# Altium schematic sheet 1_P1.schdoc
size 1198 x 850 mm; Symbol: Sheet-Symbol_A4; Device: Sheet-Symbol_A4; Company: 嘉立创EDA; Version: V1.0; Page Size: A4; @Project Name: 紫金hulu; @Page Count: 1; @Update Date: 2024-11-23; @Create Date: 2024-09-02; @Schematic Name: Schematic1; @Page No: 1; @Page Name: P1; @Board Name: Board1; @Create Time: 22:13:04; @Update Time: 17:30:21; Width: 2338; Height: 1652; Region Start: 1; X Region Count: 6; Y Region Count: 4; Blade Width: 10; Title Block Position: 3
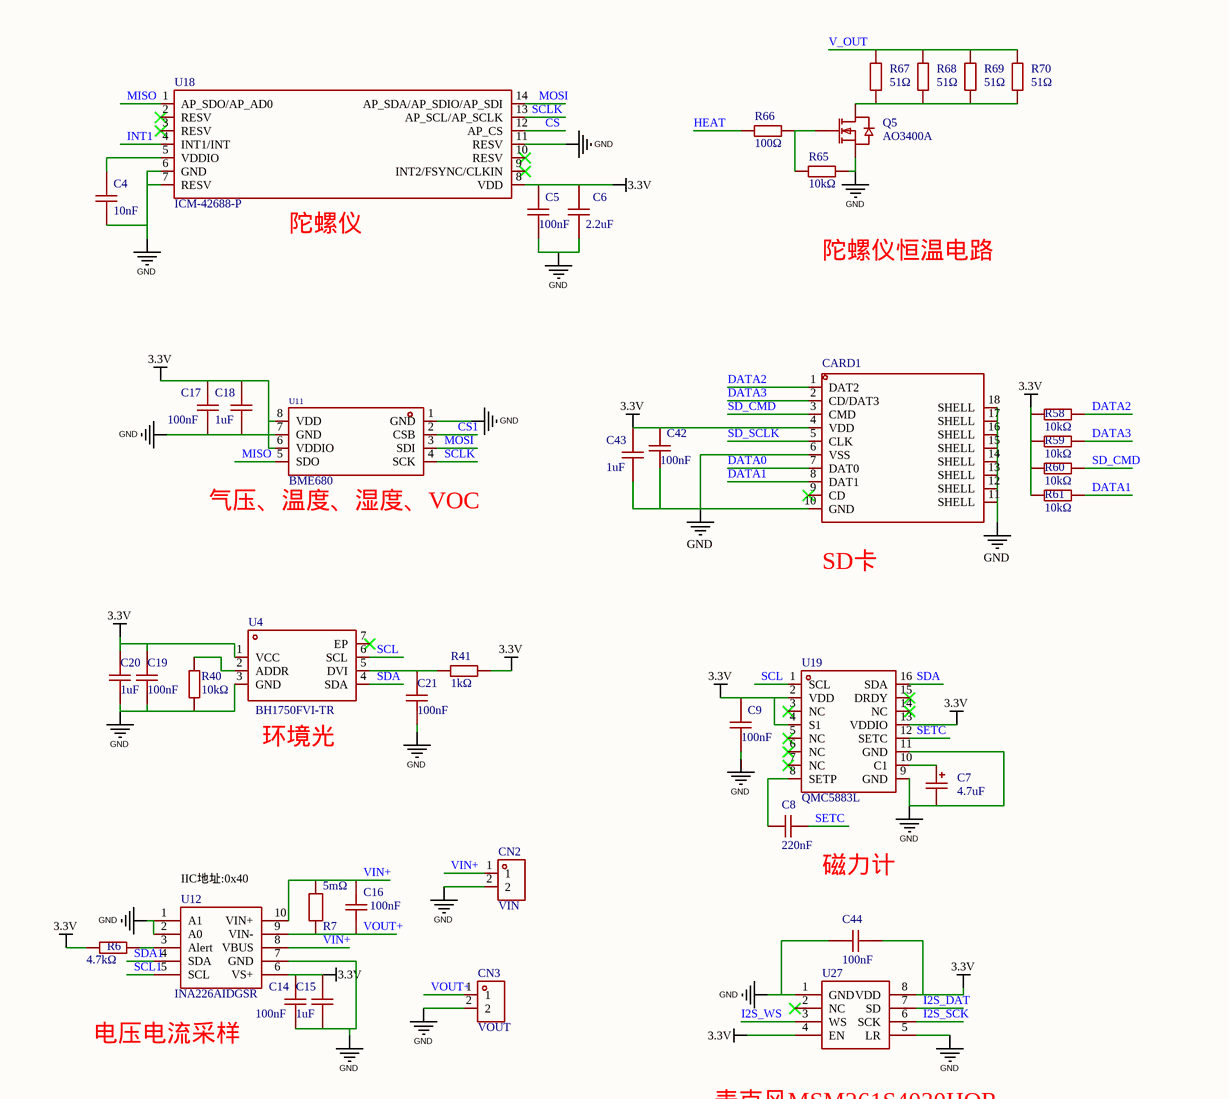
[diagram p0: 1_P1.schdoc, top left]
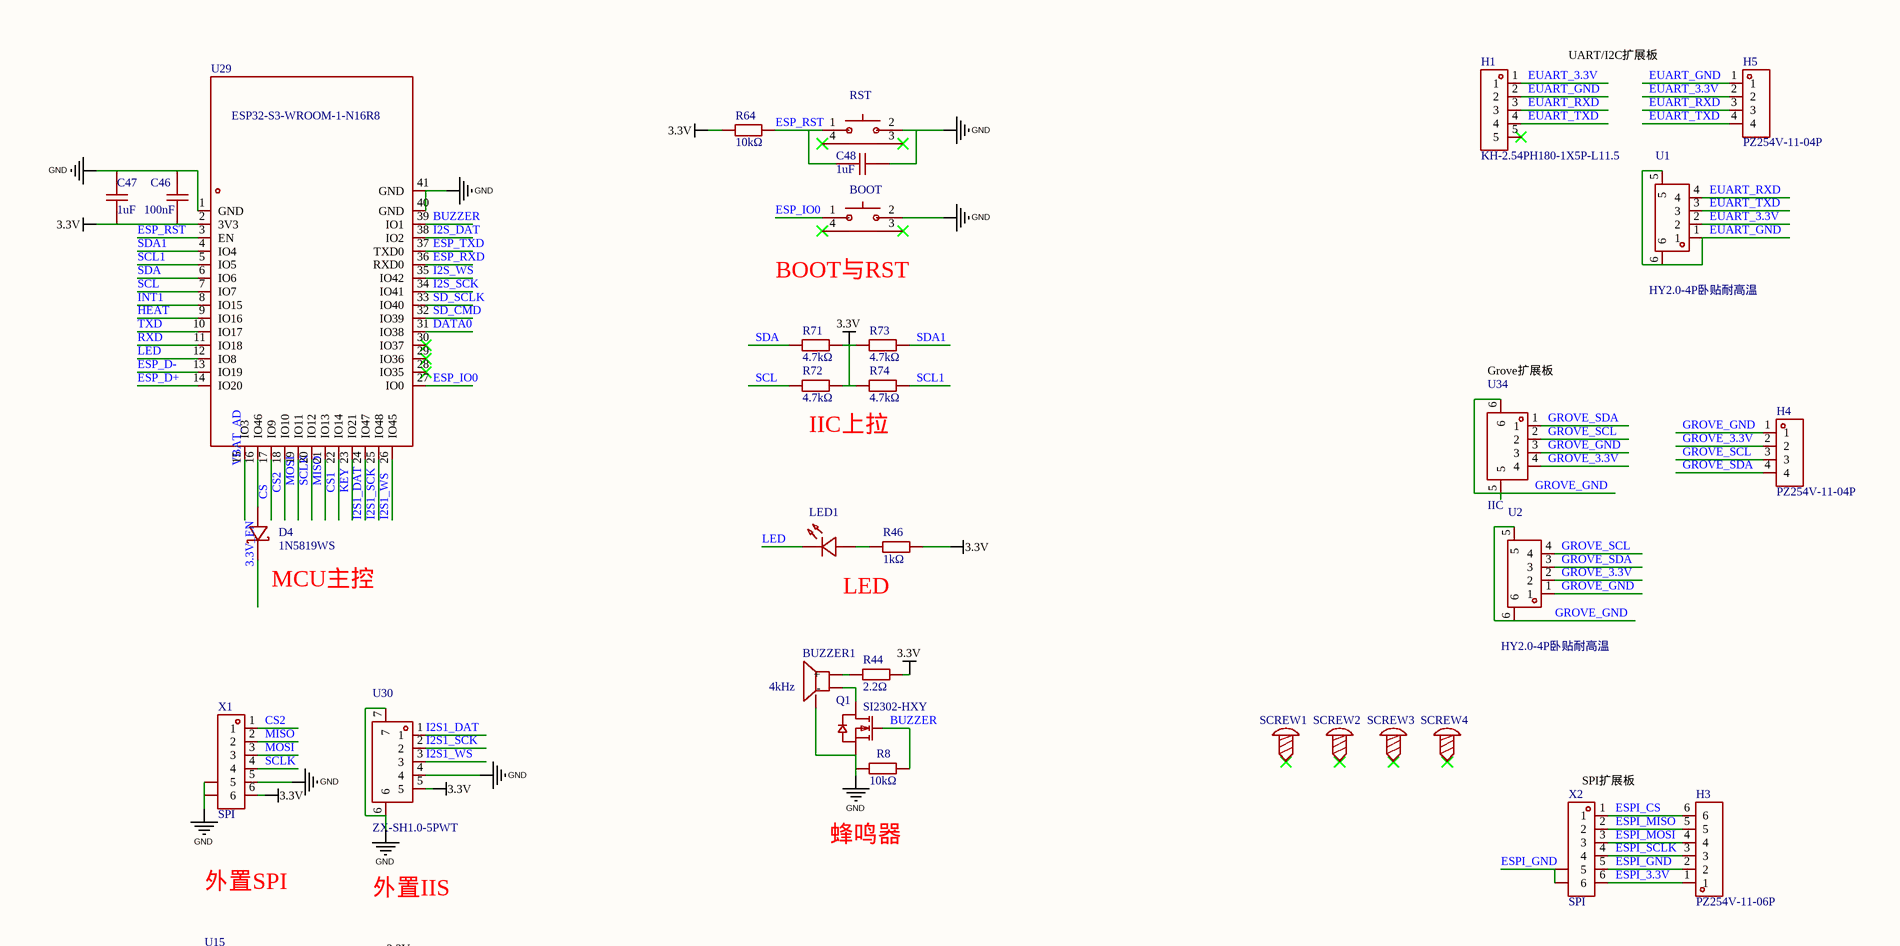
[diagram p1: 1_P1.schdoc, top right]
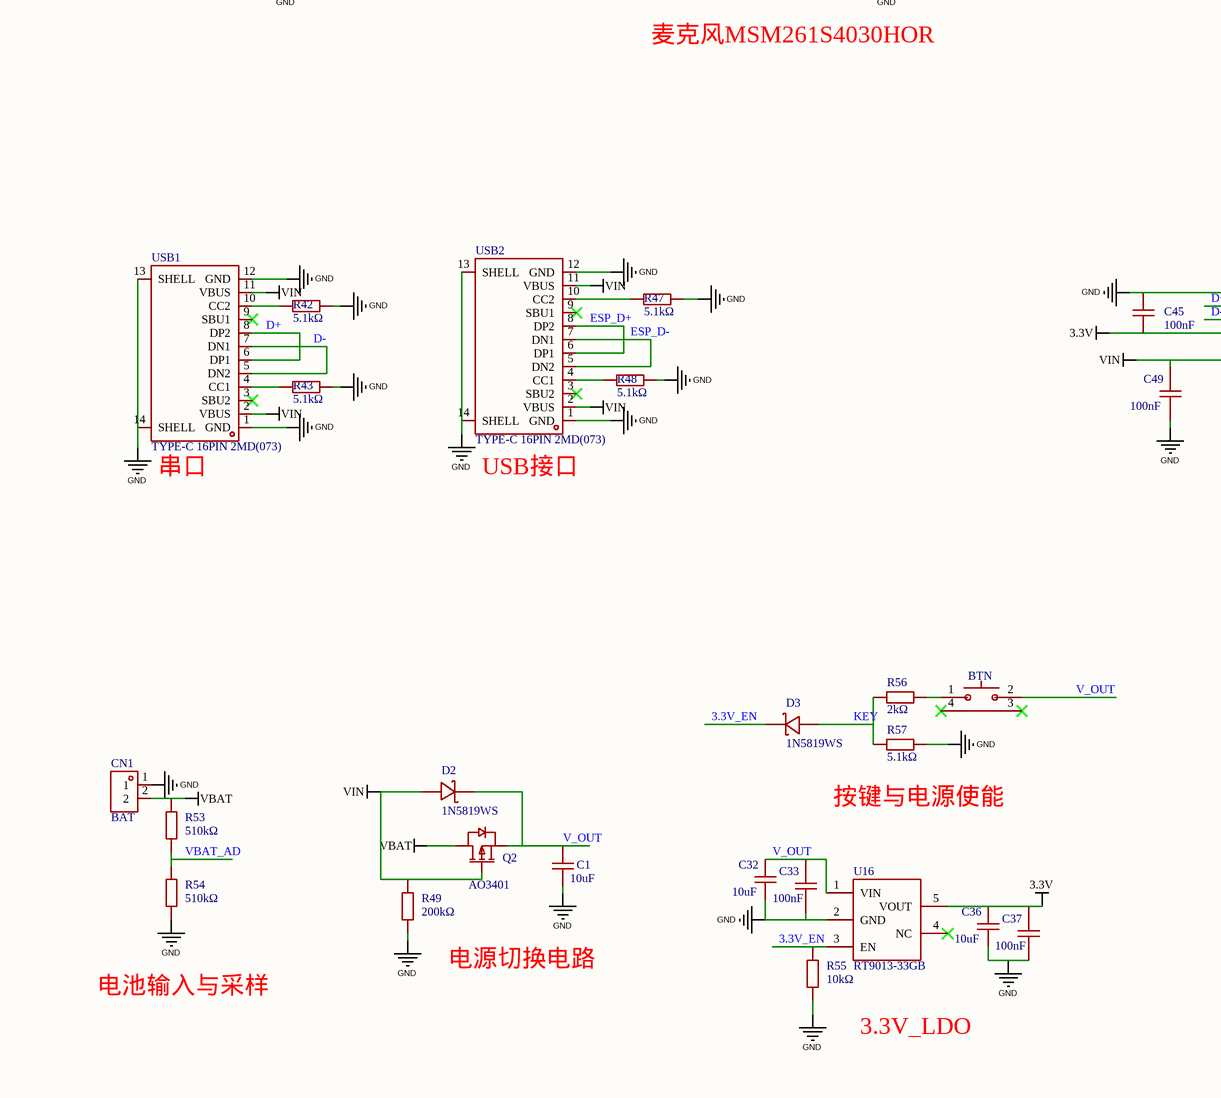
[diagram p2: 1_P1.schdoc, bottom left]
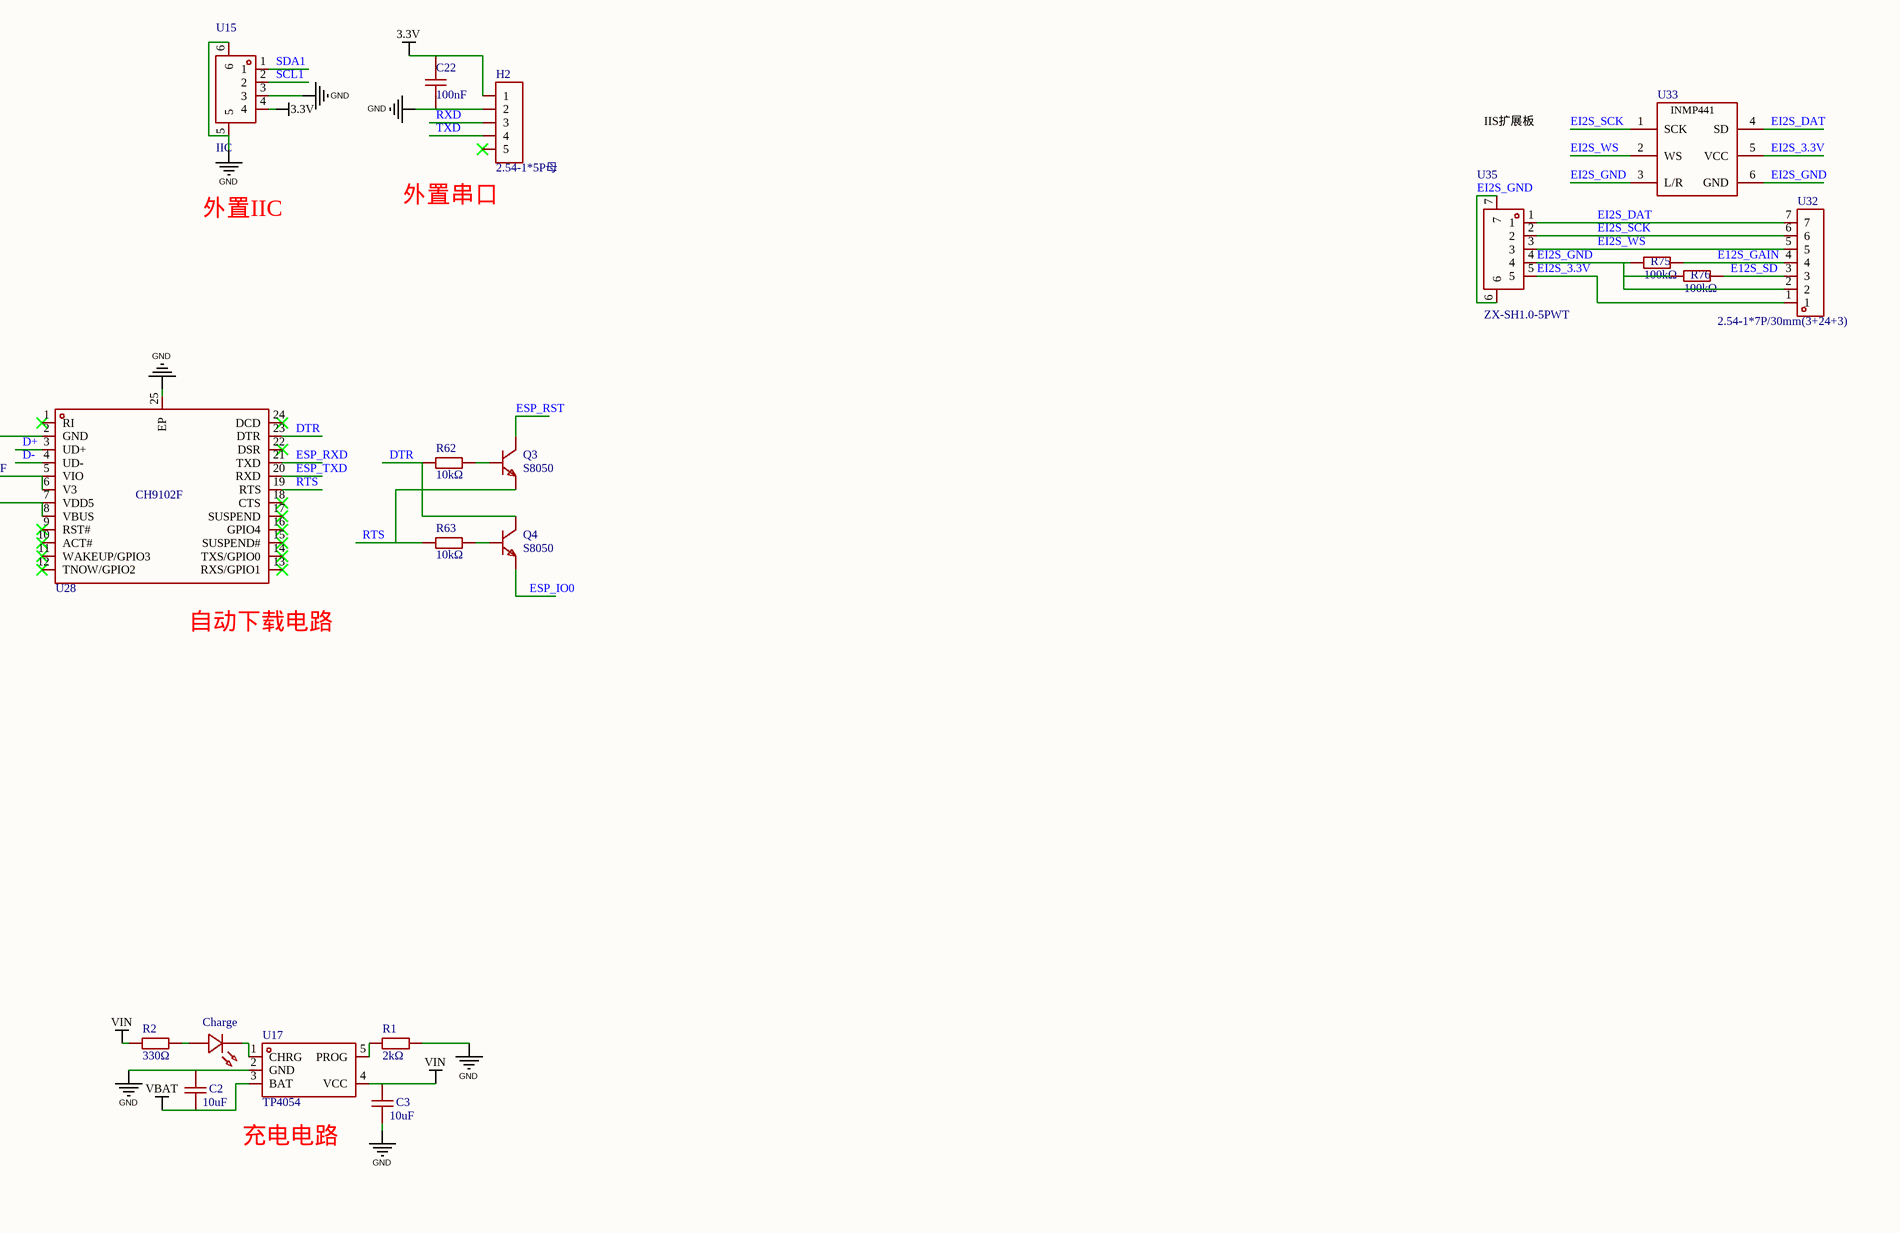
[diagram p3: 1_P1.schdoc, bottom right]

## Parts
BOOT  1TS003B-1800-3500A-CT  [SW-SMD_1TS003B-XXXX-3500A-CT]  (value not drawn)
BTN  1TS003B-1800-3500A-CT  [SW-SMD_1TS003B-XXXX-3500A-CT]  (value not drawn)
BUZZER1  4kHz  [BUZ-SMD_L5.0-W5.5-P4.60]  (value not drawn)
C1  10uF  [C0402]  (value not drawn)
C2  10uF  [C0402]  (value not drawn)
C3  10uF  [C0402]  (value not drawn)
C4  10nF  [C0402]  (value not drawn)
C5  100nF  [C0402]  (value not drawn)
C6  2.2uF  [C0402]  (value not drawn)
C7  4.7uF  [CASE-A_3216]  (value not drawn)
C8  220nF  [C0402]  (value not drawn)
C9  100nF  [C0402]  (value not drawn)
C14  100nF  [C0402]  (value not drawn)
C15  1uF  [C0402]  (value not drawn)
C16  100nF  [C0402]  (value not drawn)
C17  100nF  [C0402]  (value not drawn)
C18  1uF  [C0402]  (value not drawn)
C19  100nF  [C0402]  (value not drawn)
C20  1uF  [C0402]  (value not drawn)
C21  100nF  [C0402]  (value not drawn)
C22  100nF  [C0402]  (value not drawn)
C32  10uF  [C0402]  (value not drawn)
C33  100nF  [C0402]  (value not drawn)
C36  10uF  [C0402]  (value not drawn)
C37  100nF  [C0402]  (value not drawn)
C42  100nF  [C0402]
C43  1uF  [C0402]  (value not drawn)
C44  100nF  [C0402]  (value not drawn)
C45  100nF  [C0402]
C46  100nF  [C0402]  (value not drawn)
C47  1uF  [C0402]  (value not drawn)
C48  1uF  [C0402]  (value not drawn)
C49  100nF  [C0402]  (value not drawn)
CARD1  TF-110  [TF-SMD_TF-110]  (value not drawn)
Charge  XL-1608SURC-06  [LED0603-RD_RED]  (value not drawn)
CN1  BAT  [CONN-TH_2P-P2.5_XH2.54-2P_H]  (value not drawn)
CN2  VIN  [CONN-TH_2P-P2.5_XH2.54-2P_H]  (value not drawn)
CN3  VOUT  [CONN-TH_2P-P2.5_XH2.54-2P_H]  (value not drawn)
D2  1N5819WS  [SOD-323_L1.8-W1.3-LS2.5-RD]  (value not drawn)
D3  1N5819WS  [SOD-323_L1.8-W1.3-LS2.5-RD]  (value not drawn)
D4  1N5819WS  [SOD-323_L1.8-W1.3-LS2.5-RD]  (value not drawn)
H1  KH-2.54PH180-1X5P-L11.5  [HDR-TH_5P-P2.54-V-M]  (value not drawn)
H2  2.54-1*5P母  [HDR-TH_5P-P2.54-V-F]  (value not drawn)
H3  PZ254V-11-06P  [HDR-TH_6P-P2.54-V-M]  (value not drawn)
H4  PZ254V-11-04P  [HDR-TH_4P-P2.54-V-M]  (value not drawn)
H5  PZ254V-11-04P  [HDR-TH_4P-P2.54-V-M]  (value not drawn)
LED1  XL-1608SURC-06  [LED0603-RD_RED]  (value not drawn)
Q1  SI2302-HXY  [SOT-23-3_L2.9-W1.3-P1.90-LS2.4-BR]  (value not drawn)
Q2  AO3401  [SOT-23-3_L2.9-W1.4-P1.90-LS2.6-BR]  (value not drawn)
Q3  S8050  [SOT-23-3_L2.9-W1.6-P1.90-LS2.8-BR]  (value not drawn)
Q4  S8050  [SOT-23-3_L2.9-W1.6-P1.90-LS2.8-BR]  (value not drawn)
Q5  AO3400A  [SOT-23-3_L2.9-W1.3-P1.90-LS2.4-BR]  (value not drawn)
R1  2kΩ  [R0402]  (value not drawn)
R2  330Ω  [R0402]  (value not drawn)
R6  4.7kΩ  [R0402]  (value not drawn)
R7  5mΩ  [RES-SMD_L6.4-W3.2-R2512]  (value not drawn)
R8  10kΩ  [R0402]  (value not drawn)
R40  10kΩ  [R0402]  (value not drawn)
R41  1kΩ  [R0402]  (value not drawn)
R42  5.1kΩ  [R0402]  (value not drawn)
R43  5.1kΩ  [R0402]  (value not drawn)
R44  2.2Ω  [R0402]  (value not drawn)
R46  1kΩ  [R0402]  (value not drawn)
R47  5.1kΩ  [R0402]  (value not drawn)
R48  5.1kΩ  [R0402]  (value not drawn)
R49  200kΩ  [R0402]  (value not drawn)
R53  510kΩ  [R0402]  (value not drawn)
R54  510kΩ  [R0402]  (value not drawn)
R55  10kΩ  [R0402]  (value not drawn)
R56  2kΩ  [R0402]  (value not drawn)
R57  5.1kΩ  [R0402]  (value not drawn)
R58  10kΩ  [R0402]  (value not drawn)
R59  10kΩ  [R0402]  (value not drawn)
R60  10kΩ  [R0402]  (value not drawn)
R61  10kΩ  [R0402]  (value not drawn)
R62  10kΩ  [R0402]  (value not drawn)
R63  10kΩ  [R0402]  (value not drawn)
R64  10kΩ  [R0402]  (value not drawn)
R65  10kΩ  [R0402]  (value not drawn)
R66  100Ω  [R0402]  (value not drawn)
R67  51Ω  [R0603]  (value not drawn)
R68  51Ω  [R0603]  (value not drawn)
R69  51Ω  [R0603]  (value not drawn)
R70  51Ω  [R0603]  (value not drawn)
R71  4.7kΩ  [R0402]  (value not drawn)
R72  4.7kΩ  [R0402]  (value not drawn)
R73  4.7kΩ  [R0402]  (value not drawn)
R74  4.7kΩ  [R0402]  (value not drawn)
R75  100kΩ  [R0402]  (value not drawn)
R76  100kΩ  [R0402]  (value not drawn)
RST  1TS003B-1800-3500A-CT  [SW-SMD_1TS003B-XXXX-3500A-CT]  (value not drawn)
SCREW1  M2螺丝  [M2螺丝]  (value not drawn)
SCREW2  M2螺丝  [M2螺丝]  (value not drawn)
SCREW3  M2螺丝  [M2螺丝]  (value not drawn)
SCREW4  M2螺丝  [M2螺丝]  (value not drawn)
U1  HY2.0-4P卧贴耐高温  [CONN-SMD_C9900014118]  (value not drawn)
U2  HY2.0-4P卧贴耐高温  [CONN-SMD_C9900014118]  (value not drawn)
U4  BH1750FVI-TR  [WSOF-6_L2.6-W1.6-P0.50-TL-EP]  (value not drawn)
U11  BME680  [LGA-8_L3.0-W3.0-P0.80-TR]  (value not drawn)
U12  INA226AIDGSR  [MSOP-10_L3.0-W3.0-P0.50-LS5.0-BL]  (value not drawn)
U15  IIC  [CONN-SMD_4P-P1.00_MEGASTAR_ZX-SH1.0-4PWT]  (value not drawn)
U16  RT9013-33GB  [SOT-23-5_L3.0-W1.7-P0.95-LS2.8-BL]  (value not drawn)
U17  TP4054  [TSOT-23-5_L2.9-W1.6-P0.95-LS2.8-BR]  (value not drawn)
U18  ICM-42688-P  [LGA-14_L3.0-W2.5-P0.50-TL]  (value not drawn)
U19  QMC5883L  [LGA-16_L3.0-W3.0-P0.50-BL_SQ]  (value not drawn)
U27  MSM261S4030H0  [MSM-MIC]  (value not drawn)
U28  CH9102F  [QFN-24_L4.0-W4.0-P0.50-BL-EP2.5]  (value not drawn)
U29  ESP32-S3-WROOM-1-N16R8  [WIRELM-SMD_ESP32-S3-WROOM-1]  (value not drawn)
U30  ZX-SH1.0-5PWT  [CONN-SMD_5P-P1.00_MEGASTAR_ZX-SH1.0-5PWT]  (value not drawn)
U32  2.54-1*7P/30mm(3+24+3)  [HDR-TH_7P-P2.54-V-M-1]  (value not drawn)
U33  inmp441  [INMP441]  (value not drawn)
U34  IIC  [CONN-SMD_4P-P1.00_MEGASTAR_ZX-SH1.0-4PWT]  (value not drawn)
U35  ZX-SH1.0-5PWT  [CONN-SMD_5P-P1.00_MEGASTAR_ZX-SH1.0-5PWT]  (value not drawn)
USB1  TYPE-C 16PIN 2MD(073)  [USB-C-SMD_TYPE-C-6PIN-2MD-073]  (value not drawn)
USB2  TYPE-C 16PIN 2MD(073)  [USB-C-SMD_TYPE-C-6PIN-2MD-073]  (value not drawn)
X1  SPI  [CONN-SMD_AFC10-S06QCA-00]  (value not drawn)
X2  SPI  [CONN-SMD_AFC10-S06QCA-00]  (value not drawn)

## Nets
3.3V: C5.2 C6.2 C9.2 C14.2 C15.2 C17.2 C18.2 C19.2 C20.2 C22.2 C36.2 C37.2 C42.2 C43.2 C44.1 C45.1 C46.1 C47.1 CARD1.4(VDD) H2.1 R6.1 R41.2 R44.2 R46.2 R58.1 R59.1 R60.1 R61.1 R64.1 R71.2 R72.2 R73.1 R74.1 U4.1(VCC) U11.6(VDDIO) U11.8(VDD) U12.6(VS+) U15.4 U16.5(VOUT) U18.8(VDD) U19.2(VDD) U19.4(S1) U19.13(VDDIO) U27.4(EN) U27.8(VDD) U28.5(VIO) U28.6(V3) U29.2(3V3) U30.5 X1.6
GND: BOOT.2 BUZZER1.3(NC) C1.1 C2.2 C3.1 C4.2 C5.1 C6.1 C7.2 C9.1 C14.1 C15.1 C17.1 C18.1 C19.1 C20.1 C21.1 C22.1 C32.1 C33.1 C36.1 C37.1 C42.1 C43.1 C44.2 C45.2 C46.2 C47.2 C48.2 C49.1 CARD1.6(VSS) CARD1.10(GND) CARD1.11(SHELL) CARD1.12(SHELL) CARD1.13(SHELL) CARD1.14(SHELL) CARD1.15(SHELL) CARD1.16(SHELL) CARD1.17(SHELL) CARD1.18(SHELL) CN1.1 CN2.2 CN3.2 H2.2 Q1.2(S) Q5.2(S) R1.2 R8.1 R40.1 R42.2 R43.2 R47.2 R48.2 R49.1 R54.1 R55.1 R57.2 R65.2 RST.2 U4.3(GND) U11.1(GND) U11.7(GND) U12.1(A1) U12.2(A0) U12.7(GND) U15.3 U15.5 U15.6 U16.2(GND) U17.2(GND) U18.6(GND) U18.7(RESV) U18.11(RESV) U19.9(GND) U19.11(GND) U27.1(GND) U27.5(LR) U28.2(GND) U28.25(EP) U29.1(GND) U29.40(GND) U29.41(GND) U30.4 U30.6 U30.7 USB1.1(GND) USB1.12(GND) USB1.13(SHELL) USB1.14(SHELL) USB2.1(GND) USB2.12(GND) USB2.13(SHELL) USB2.14(SHELL) X1.5 X1.7 X1.8
VBAT: C2.1 CN1.2 Q2.3(D) R53.2 U17.3(BAT)
VIN: C3.2 C49.2 D2.2(A) Q2.1(G) R2.1 R49.2 U17.4(VCC) U28.7(VDD5) U28.8(VBUS) USB1.2(VBUS) USB1.11(VBUS) USB2.2(VBUS) USB2.11(VBUS)
3.3V_EN: D3.1(K) D4.1(K) R55.2 U16.3(EN)
BUZZER: Q1.1(G) R8.2 U29.39(IO1)
CS: U18.12(AP_CS) U29.17(IO9)
CS1: U11.2(CSB) U29.22(IO14)
CS2: U29.18(IO10) X1.1
D+: U28.3(UD+) USB1.6(DP1) USB1.8(DP2)
D-: U28.4(UD-) USB1.5(DN2) USB1.7(DN1)
DATA0: CARD1.7(DAT0) U29.31(IO38)
DATA1: CARD1.8(DAT1) R61.2
DATA2: CARD1.1(DAT2) R58.2
DATA3: CARD1.2(CD/DAT3) R59.2
DTR: Q4.3 R62.1 U28.23(DTR)
E12S_GAIN: R75.2 U32.4
E12S_SD: R76.2 U32.3
EI2S_3.3V: U32.1 U33.5(VCC) U35.5
EI2S_DAT: U32.7 U33.4(SD) U35.1
EI2S_GND: R75.1 R76.1 U32.2 U33.3(L/R) U33.6(GND) U35.4 U35.6 U35.7
EI2S_SCK: U32.6 U33.1(SCK) U35.2
EI2S_WS: U32.5 U33.2(WS) U35.3
ESP_D+: U29.14(IO20) USB2.6(DP1) USB2.8(DP2)
ESP_D-: U29.13(IO19) USB2.5(DN2) USB2.7(DN1)
ESP_IO0: BOOT.1 Q4.2 U29.27(IO0)
ESP_RST: C48.1 Q3.3 R64.2 RST.1 U29.3(EN)
ESP_RXD: U28.21(TXD) U29.36(RXD0)
ESP_TXD: U28.20(RXD) U29.37(TXD0)
ESPI_3.3V: H3.1 X2.6
ESPI_CS: H3.6 X2.1
ESPI_GND: H3.2 X2.5 X2.7 X2.8
ESPI_MISO: H3.5 X2.2
ESPI_MOSI: H3.4 X2.3
ESPI_SCLK: H3.3 X2.4
EUART_3.3V: H1.1 H5.2 U1.2
EUART_GND: H1.2 H5.1 U1.1 U1.5 U1.6
EUART_RXD: H1.3 H5.3 U1.4
EUART_TXD: H1.4 H5.4 U1.3
GROVE_3.3V: H4.2 U2.2 U34.4
GROVE_GND: H4.1 U2.1 U2.5 U2.6 U34.3 U34.5 U34.6
GROVE_SCL: H4.3 U2.4 U34.2
GROVE_SDA: H4.4 U2.3 U34.1
HEAT: R66.1 U29.9(IO16)
I2S1_DAT: U29.24(IO47) U30.1
I2S1_SCK: U29.25(IO48) U30.2
I2S1_WS: U29.26(IO45) U30.3
I2S_DAT: U27.7(SD) U29.38(IO2)
I2S_SCK: U27.6(SCK) U29.34(IO41)
I2S_WS: U27.3(WS) U29.35(IO42)
INT1: U18.4(INT1/INT) U29.8(IO15)
KEY: D3.2(A) R56.2 R57.1 U29.23(IO21)
LED: LED1.1(K) U29.12(IO8)
MISO: U11.5(SDO) U18.1(AP_SDO/AP_AD0) U29.21(IO13) X1.2
MOSI: U11.3(SDI) U18.14(AP_SDA/AP_SDIO/AP_SDI) U29.19(IO11) X1.3
RTS: Q3.2 R63.1 U28.19(RTS)
RXD: H2.3 U29.11(IO18)
SCL: R72.1 U4.6(SCL) U19.1(SCL) U29.7(IO7)
SCL1: R74.2 U12.5(SCL) U15.2 U29.5(IO5)
SCLK: U11.4(SCK) U18.13(AP_SCL/AP_SCLK) U29.20(IO12) X1.4
SD_CMD: CARD1.3(CMD) R60.2 U29.32(IO39)
SD_SCLK: CARD1.5(CLK) U29.33(IO40)
SDA: R71.1 U4.4(SDA) U19.16(SDA) U29.6(IO6)
SDA1: R73.2 U12.4(SDA) U15.1 U29.4(IO4)
SETC: C8.2 U19.12(SETC)
TXD: H2.4 U29.10(IO17)
V_OUT: BTN.2 C1.2 C32.2 C33.2 D2.1(K) Q2.2(S) R67.2 R68.2 R69.2 R70.2 U16.1(VIN)
VBAT_AD: R53.1 R54.2 U29.15(IO3)
VIN+: C16.2 CN2.1 R7.2 U12.8(VBUS) U12.10(VIN+)
VOUT+: C16.1 CN3.1 R7.1 U12.9(VIN-)
NetBTN_1: BTN.1 R56.1
NetBUZZER1_1: BUZZER1.1(+) R44.1
NetBUZZER1_2: BUZZER1.2(-) Q1.3(D)
NetC4_1: C4.1 U18.5(VDDIO)
NetC7_1: C7.1 U19.10(C1)
NetC8_1: C8.1 U19.8(SETP)
NetC21_2: C21.2 R41.1 U4.5(DVI)
NetCharge_1: Charge.1(K) U17.1(CHRG)
NetCharge_2: Charge.2(A) R2.2
NetD4_2: D4.2(A) U29.16(IO46)
NetLED1_2: LED1.2(A) R46.1
NetQ3_1: Q3.1 R62.2
NetQ4_1: Q4.1 R63.2
NetQ5_1: Q5.1(G) R65.1 R66.2
NetQ5_3: Q5.3(D) R67.1 R68.1 R69.1 R70.1
NetR1_1: R1.1 U17.5(PROG)
NetR6_2: R6.2 U12.3(Alert)
NetR40_2: R40.2 U4.2(ADDR)
NetR42_1: R42.1 USB1.10(CC2)
NetR43_1: R43.1 USB1.4(CC1)
NetR47_1: R47.1 USB2.10(CC2)
NetR48_1: R48.1 USB2.4(CC1)

Not connected (* = marked no-connect by the designer): BOOT 3* 4*; BTN 3* 4*; CARD1 9(CD)*; H1 5*; H2 5*; RST 3* 4*; SCREW1 1*; SCREW2 1*; SCREW3 1*; SCREW4 1*; U4 7(EP)*; U16 4(NC)*; U18 2(RESV)* 3(RESV)* 9(INT2/FSYNC/CLKIN)* 10(RESV)*; U19 3(NC)* 5(NC)* 6(NC)* 7(NC)* 14(NC)* 15(DRDY)*; U27 2(NC)*; U28 1(RI)* 9(RST#)* 10(ACT#)* 11(WAKEUP/GPIO3)* 12(TNOW/GPIO2)* 13(RXS/GPIO1)* 14(TXS/GPIO0)* 15(SUSPEND#)* 16(GPIO4)* 17(SUSPEND)* 18(CTS)* 22(DSR)* 24(DCD)*; U29 28(IO35)* 29(IO36)* 30(IO37)*; USB1 3(SBU2)* 9(SBU1)*; USB2 3(SBU2)* 9(SBU1)*

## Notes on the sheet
- UART/I2C扩展板
- (near U18) 陀螺仪
- 陀螺仪恒温电路
- (near BOOT) BOOT与RST
- (near U34) Grove扩展板
- IIC上拉
- (near U11) 气压、温度、湿度、VOC
- (near CARD1) SD卡
- (near D4) MCU主控
- LED
- (near U4) 环境光
- (near X2) SPI扩展板
- 蜂鸣器
- (near U12) IIC地址:0x40
- 磁力计
- 外置SPI
- 外置IIS
- 电压电流采样
- IIS扩展板
- 麦克风MSM261S4030HOR
- 外置IIC
- 外置串口
- (near USB1) 串口
- (near USB2) USB接口
- (near U28) 自动下载电路
- (near R57) 按键与电源使能
- 电池输入与采样
- (near R49) 电源切换电路
- 3.3V_LDO
- 充电电路

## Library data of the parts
BOOT BTN RST = 1TS003B-1800-3500A-CT: 电路结构:单刀单掷;按钮形状:矩形按钮;作用力:180gf;安装方式:卧贴;开关长度:4.6mm;开关宽度:1.82mm;开关高度:3.5mm;带支架:不带;触点电流:50mA;额定电压(AC):-;额定电压(DC):12V;额定功率:0.6W;绝缘电阻:100MΩ;带灯:无;机械寿命:5万次;; Manufacturer: HYP(鸿源精密); Add into BOM: yes; Circuit: 单刀单掷; Actuator Style: 矩形按钮; Operating Force: 180gf; Switch Length: 4.6mm; Switch Width: 1.82mm; Switch Height: 3.5mm; Strike Gundam: 不带; Contact Current: 50mA; Voltage Rating (DC): 12V; Power Rating: 0.6W; Insulation Resistance: 100MΩ; Actuator/Cap Color: 黑色; With Lamp: 无; Pin Style: J型引脚; Mechanical Life: 5万次
BUZZER1 = MLT-5020: 驱动方式:无源(外部驱动);构造类型:电磁式;频率:4kHz;; Manufacturer: 华能; Add into BOM: yes; Technology Type: 电磁式
C1-C3 C32 C36 = CL05A106MQ5NUNC: 容值:10uF;精度:±20%;额定电压:6.3V;材质(温度系数):X5R;; Manufacturer: SAMSUNG(三星); Add into BOM: yes; Tolerance: ±20%; Voltage Rated: 6.3V; Temperature Coefficient: X5R
C4 = CC0402KRX7R7BB103: 容值:10nF;精度:±10%;额定电压:16V;材质(温度系数):X7R;; Manufacturer: YAGEO(国巨); Add into BOM: yes; Tolerance: ±10%; Voltage Rated: 16V; Temperature Coefficient: X7R
C5 C9 C14 C16 C17 C19 C21 C22 C33 C37 C44 C46 C49 = CC0402KRX7R7BB104: 容值:100nF;精度:±10%;额定电压:16V;材质(温度系数):X7R;; Manufacturer: YAGEO(国巨); Add into BOM: yes; Tolerance: ±10%; Voltage Rated: 16V; Temperature Coefficient: X7R
C6 = GRM155R61E225KE11D: 容值:2.2uF;精度:±10%;额定电压:25V;材质(温度系数):X5R;; Manufacturer: muRata(村田); Add into BOM: yes; Tolerance: ±10%; Voltage Rated: 25V; Temperature Coefficient: X5R
C7 = TAJA475K016RNJ: 容值:4.7uF;精度:±10%;额定电压:16V;等效串联电阻:4Ω@100kHz;; Manufacturer: Kyocera AVX; Add into BOM: yes; Tolerance: ±10%; Rated Voltage: 16V
C8 = CL05B224KO5NNNC: 容值:220nF;精度:±10%;额定电压:16V;材质(温度系数):X7R;; Manufacturer: SAMSUNG(三星); Add into BOM: yes; Tolerance: ±10%; Voltage Rated: 16V; Temperature Coefficient: X7R
C15 C18 C20 C43 C47 C48 = C1005X5R105KCTS: 容值:1uF;精度:±10%;额定电压:6.3V;材质(温度系数):X5R;; Manufacturer: DARFON(达方); Add into BOM: yes; Tolerance: ±10%; Voltage Rated: 6.3V; Temperature Coefficient: X5R
C42 C45 = 0603B104K500NT: 容值:100nF;精度:±10%;额定电压:50V;材质(温度系数):X7R;; Manufacturer: FH(风华); Add into BOM: yes; Tolerance: ±10%; Voltage Rated: 50V; Temperature Coefficient: X7R
CARD1 = TF-110: 卡连接方式:拔插式;卡类型:MicroSD卡(TF卡);连接器类型:卡座;本体最大高度:1.32mm;触头材质:磷铜;触头镀层:金;工作温度范围:-45~+85;焊接温度(最大值):260;; Manufacturer: XUNPU(讯普); Add into BOM: yes; Card Connection Mode: 拔插式; Connector Type: 卡座; Maximum Body Height: 1.32mm; Welding Temperature (Max): 260
Charge LED1 = XL-1608SURC-06: 发光颜色:红色;功率:55mW;正向电流:25mA;主波长:617nm~621nm;透镜颜色:无色透明透镜;色温:-;发光角度:120°;载带方式:正贴;工作温度:-30℃~+85℃;; Manufacturer: XINGLIGHT(成兴光); Add into BOM: yes; Emitted Color: 红色; Power Dissipation: 55mW; Forward Current: 25mA; Peak Wavelength: 623nm; Lens Color: 无色透明透镜; Viewing Angle: 120°; Mounting Sytle: 正贴
CN1-CN3 = XH2.54-2P_H弯针插座: Add into BOM: yes
D2-D4 = 1N5819WS_C191023: 正向压降(Vf):600mV@1A;直流反向耐压(Vr):40V;平均整流电流(Io):1A;; Manufacturer: Hottech(合科泰); Add into BOM: yes; Reverse Voltage (Vr): 40V; Average Rectified Current (Io): 1A
H1 = KH-2.54PH180-1X5P-L11.5: 插针结构:1x5P;间距:2.54mm;行距:-;圆针/方针:方针;安装类型:直插;排数:单排;总PIN位数:5P;额定电流:3A;额定电压:-;配合针长度:6mm;塑高:2.5mm;端接针长度:3mm;工作温度范围:-40℃~+105℃;颜色:黑色;; Manufacturer: kinghelm(金航标); Add into BOM: yes; Pin Structure: 1x5P; Pitch: 2.54mm; Circluar Pins/Square Pins: 方针; Current Rating (Max): 3A
H2 = 2.54-1*5P母: 插孔结构:1x5P;间距:2.54mm;行距:-;安装类型:直插;排数:单排;总孔位数:5P;塑高:-;触头材质:-;触头镀层:-;; Manufacturer: BOOMELE(博穆精密); Symbol: Header-Female-2.54_1x5; Add into BOM: yes; Holes Structure: 1x5P; Pitch: 2.54mm; Number of Holes: 5P
H3 = PZ254V-11-06P: 插针结构:1x6P;间距:2.54mm;行距:-;圆针/方针:方针;安装类型:直插;排数:单排;总PIN位数:6P;额定电流:-;额定电压:-;配合针长度:6mm;塑高:2.5mm;端接针长度:3mm;触头材质:黄铜;触头镀层:-;工作温度范围:-40℃~+105℃;颜色:黑色;; Manufacturer: XFCN(兴飞); Add into BOM: yes; Pin Structure: 1x6P; Pitch: 2.54mm; Circluar Pins/Square Pins: 方针
H4 H5 = PZ254V-11-04P: 插针结构:1x4P;间距:2.54mm;行距:-;圆针/方针:方针;安装类型:直插;排数:单排;总PIN位数:4P;额定电流:3A;额定电压:250V;配合针长度:6mm;塑高:2.5mm;端接针长度:3mm;触头材质:-;工作温度范围:-40℃~+105℃;颜色:黑色;; Manufacturer: XFCN(兴飞); Symbol: PZ254V-11-04P_C2691448; Add into BOM: yes; Pin Structure: 1x4P; Pitch: 2.54mm; Circluar Pins/Square Pins: 方针; Current Rating (Max): 3A; Voltage Rating (Max): 250V
Q1 = SI2302-HXY: 类型:1个N沟道;漏源电压(Vdss):20V;连续漏极电流(Id):2.8A;功率(Pd):900mW;导通电阻(RDS(on)@Vgs,Id):55mΩ@4.5V,2.8A;阈值电压(Vgs(th)@Id):1.2V@250uA;; Manufacturer: HXY MOSFET(华轩阳电子); Symbol: SI2302_C4748714; Add into BOM: yes; Type: 1个N沟道; Drain Source Voltage (Vdss): 20V; Power Dissipation (Pd): 900mW; Input Capacitance (Ciss@Vds): 260pF@10V
Q2 = AO3401_C727156: 类型:1个P沟道;漏源电压(Vdss):30V;连续漏极电流(Id):4.2A;功率(Pd):350mW;导通电阻(RDS(on)@Vgs,Id):65mΩ@10V,4.2A;阈值电压(Vgs(th)@Id):1.3V@250uA;; Manufacturer: TWGMC(台湾迪嘉); Add into BOM: yes; Type: 1个P沟道; Drain Source Voltage (Vdss): 30V; Power Dissipation (Pd): 350mW
Q3 Q4 = S8050_C181158: 晶体管类型:NPN;集电极电流(Ic):500mA;集射极击穿电压(Vceo):25V;功率(Pd):300mW;; Manufacturer: Hottech(合科泰); Add into BOM: yes; Transistor Type: NPN; Collector Current (Ic): 500mA; Collector-Emitter Breakdown Voltage (Vceo): 25V; Power Dissipation (Pd): 300mW; Transition Frequency (fT): 150MHz; Collector Cut-Off Current (Icbo): 100nA; Collector-Emitter Saturation Voltage (VCE(sat)@Ic,Ib): 600mV@500mA,50mA
Q5 = AO3400A_C20917: 类型:1个N沟道;漏源电压(Vdss):30V;连续漏极电流(Id):5.7A;功率(Pd):1.4W;导通电阻(RDS(on)@Vgs,Id):26.5mΩ@10V,5.7A;阈值电压(Vgs(th)@Id):1.5V@250uA;; Manufacturer: AOS; Add into BOM: yes; Type: 1个N沟道; Drain Source Voltage (Vdss): 30V; Power Dissipation (Pd): 1.4W; Total Gate Charge (Qg@Vgs): 7nC@4.5V; Input Capacitance (Ciss@Vds): 630pF@15V
R1 R56 = 0402WGF2001TCE: 电阻类型:厚膜电阻;阻值:2kΩ;精度:±1%;功率:62.5mW;最大工作电压:50V;温度系数:±100ppm/℃;; Manufacturer: UNI-ROYAL(厚声); Add into BOM: yes; Tolerance: ±1%; Power(Watts): 62.5mW; Overload Voltage (Max): 50V
R2 = 0402WGF3300TCE: 电阻类型:厚膜电阻;阻值:330Ω;精度:±1%;功率:62.5mW;最大工作电压:50V;温度系数:±100ppm/℃;; Manufacturer: UNI-ROYAL(厚声); Add into BOM: yes; Tolerance: ±1%; Power(Watts): 62.5mW; Overload Voltage (Max): 50V
R6 = RTT02472JTH: 电阻类型:厚膜电阻;阻值:4.7kΩ;精度:±5%;功率:62.5mW;最大工作电压:50V;温度系数:±100ppm/℃;; Manufacturer: RALEC(旺诠); Add into BOM: yes; Tolerance: ±5%; Power(Watts): 62.5mW; Overload Voltage (Max): 50V
R7 = LRAN25EJER005: 电阻类型:采样电阻;阻值:5mΩ;精度:±5%;功率:2W;; Manufacturer: NCT(利昇达); Add into BOM: yes; Tolerance: ±5%; Power(Watts): 2W
R8 R40 R55 R58-R65 = RC0402FR-0710KL: 电阻类型:厚膜电阻;阻值:10kΩ;精度:±1%;功率:62.5mW;最大工作电压:50V;温度系数:±100ppm/℃;; Manufacturer: YAGEO(国巨); Add into BOM: yes; Tolerance: ±1%; Power(Watts): 62.5mW; Overload Voltage (Max): 50V
R41 R46 = 0402WGF1001TCE: 电阻类型:厚膜电阻;阻值:1kΩ;精度:±1%;功率:62.5mW;最大工作电压:50V;温度系数:±100ppm/℃;; Manufacturer: UNI-ROYAL(厚声); Add into BOM: yes; Tolerance: ±1%; Power(Watts): 62.5mW; Overload Voltage (Max): 50V
R42 R43 R47 R48 R57 = 0402WGF5101TCE: 电阻类型:厚膜电阻;阻值:5.1kΩ;精度:±1%;功率:62.5mW;最大工作电压:50V;温度系数:±100ppm/℃;; Manufacturer: UNI-ROYAL(厚声); Add into BOM: yes; Tolerance: ±1%; Power(Watts): 62.5mW; Overload Voltage (Max): 50V
R44 = 0402WGF220KTCE: 电阻类型:厚膜电阻;阻值:2.2Ω;精度:±1%;功率:62.5mW;最大工作电压:50V;温度系数:±200ppm/℃;; Manufacturer: UNI-ROYAL(厚声); Add into BOM: yes; Tolerance: ±1%; Power(Watts): 62.5mW; Overload Voltage (Max): 50V
R49 = 0402WGF2003TCE: 电阻类型:厚膜电阻;阻值:200kΩ;精度:±1%;功率:62.5mW;最大工作电压:50V;温度系数:±100ppm/℃;; Manufacturer: UNI-ROYAL(厚声); Add into BOM: yes; Tolerance: ±1%; Power(Watts): 62.5mW; Overload Voltage (Max): 50V
R53 R54 = 0402WGF5103TCE: 电阻类型:厚膜电阻;阻值:510kΩ;精度:±1%;功率:62.5mW;最大工作电压:50V;温度系数:±100ppm/℃;; Manufacturer: UNI-ROYAL(厚声); Add into BOM: yes; Tolerance: ±1%; Power(Watts): 62.5mW; Overload Voltage (Max): 50V
R66 = 0402WGJ0101TCE: 电阻类型:厚膜电阻;阻值:100Ω;精度:±5%;功率:62.5mW;最大工作电压:50V;温度系数:±100ppm/℃;; Manufacturer: UNI-ROYAL(厚声); Add into BOM: yes; Tolerance: ±5%; Power(Watts): 62.5mW; Overload Voltage (Max): 50V
R67-R70 = 0603WAF510JT5E: 电阻类型:厚膜电阻;阻值:51Ω;精度:±1%;功率:100mW;最大工作电压:75V;温度系数:±100ppm/℃;; Manufacturer: UNI-ROYAL(厚声); Add into BOM: yes; Tolerance: ±1%; Power(Watts): 100mW; Overload Voltage (Max): 75V
R71-R74 = 0402WGJ0472TCE: 电阻类型:厚膜电阻;阻值:4.7kΩ;精度:±5%;功率:62.5mW;最大工作电压:50V;温度系数:±100ppm/℃;; Manufacturer: UNI-ROYAL(厚声); Add into BOM: yes; Tolerance: ±5%; Power(Watts): 62.5mW; Overload Voltage (Max): 50V
R75 R76 = 0402WGF1003TCE: 电阻类型:厚膜电阻;阻值:100kΩ;精度:±1%;功率:62.5mW;最大工作电压:50V;温度系数:±100ppm/℃;; Manufacturer: UNI-ROYAL(厚声); Add into BOM: yes; Tolerance: ±1%; Power(Watts): 62.5mW; Overload Voltage (Max): 50V
SCREW1-SCREW4 = M2螺丝: Symbol: 螺丝孔; Convert to PCB: yes
U1 U2 = HY2.0-4P卧贴耐高温: Add into BOM: yes
U4 = BH1750FVI-TR: 检测颜色:-;接口类型:I2C;分辨率(位):16;; Manufacturer: ROHM(罗姆); Add into BOM: yes; Interface Type: I2C; Supply Voltage: 2.4V~3.6V; Resolution: 16
U11 = BME680: 气体，湿度，压力，温度传感器; Manufacturer: Bosch(博世); Add into BOM: yes
U12 = INA226AIDGSR: INA226 支持报警功能的 36V、双向、超高精度、低侧/高侧、I2C 输出电流/功率监控器; Manufacturer: TI(德州仪器); Add into BOM: yes; Supply Voltage: 0V~36V
U15 U34 = ZX-SH1.0-4PWT: 插针结构:1x4P;间距:1mm;安装方式:卧贴;参考系列:SH;总PIN数:4P;排数:1;每排PIN数:4;行距:-;额定电流:1A;触头材质:黄铜;触头镀层:锡;工作温度范围:-25℃~+85℃;; Manufacturer: Megastar(兆星); Add into BOM: yes; Pins Structure: 1x4P; Pitch: 1mm; Reference Series: SH; Number of PINs Per Row: 4; Current Rating (Max): 1A
U16 = RT9013-33GB: 输出类型:固定;最大输入电压:5.5V;输出电压:3.3V;最大输出电流:500mA;电源纹波抑制比(PSRR):50dB@(10kHz);输出极性:正极;; Manufacturer: RICHTEK(立锜); Add into BOM: yes; Output Type: 固定; Maximum Input Voltage: 5.5V; Output Voltage: 3.3V; MAX Output Current: 500mA; Dropout Voltage: 400mV@(500mA); standby current: 50uA; Output Polarity: 正极; Number of Outputs: 1
U17 = TP4054_C668215: 电源电压:6.5V;最大充电电流:500mA;电池类型:锂离子/聚合物;电池节数:1;; Manufacturer: UMW(友台半导体); Add into BOM: yes; Supply Voltage: 6.5V; Maximum Charge Current: 500mA; Number of Cells: 1
U18 = ICM-42688-P: 传感器类型:加速度计陀螺仪;; Manufacturer: TDK InvenSense(应美盛); Add into BOM: yes
U19 = QMC5883L: Manufacturer: QST(上海矽睿); Add into BOM: yes
U27 = MSM261S4030H0: Add into BOM: yes
U28 = CH9102F: Manufacturer: WCH(南京沁恒); Add into BOM: yes
U29 = ESP32-S3-WROOM-1-N16R8: Manufacturer: ESPRESSIF(乐鑫); Symbol: ESP32-S3-WROOM-1(N16R8); Add into BOM: yes
U30 U35 = ZX-SH1.0-5PWT: 插针结构:1x5P;间距:1mm;安装方式:卧贴;参考系列:SH;总PIN数:5P;排数:1;每排PIN数:5;行距:-;额定电流:1A;触头材质:黄铜;触头镀层:锡;工作温度范围:-25℃~+85℃;; Manufacturer: Megastar(兆星); Add into BOM: yes; Pins Structure: 1x5P; Pitch: 1mm; Reference Series: SH; Number of PINs Per Row: 5; Current Rating (Max): 1A
U32 = 2.54-1*7P/30mm(3+24+3): Add into BOM: yes
U33 = inmp441: Symbol: inmp441_数字麦克风; Add into BOM: yes
USB1 USB2 = TYPE-C 16PIN 2MD(073): 连接器类型:Type-C;标准:-;公母:母;端口数量:1;触点数量:16P;安装方式:卧贴;额定电流 - 电源:5A;工作温度范围:-25℃~+85℃;; Manufacturer: SHOU HAN(首韩); Add into BOM: yes; Gender: 母; Number of Ports: 1; Number of Contacts: 16P; Current Rating - Power (Max): 5A
X1 X2 = AFC10-S06QCA-00: 插针结构:1x6P;间距:1mm;安装方式:卧贴;参考系列:SH;总PIN数:6P;排数:1;每排PIN数:6;行距:-;额定电流:500mA;工作温度范围:-25℃~+85℃;; Manufacturer: JS(钜硕电子); Add into BOM: yes; Pins Structure: 1x6P; Pitch: 1mm; Reference Series: SH; Number of PINs Per Row: 6; Current Rating (Max): 500mA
